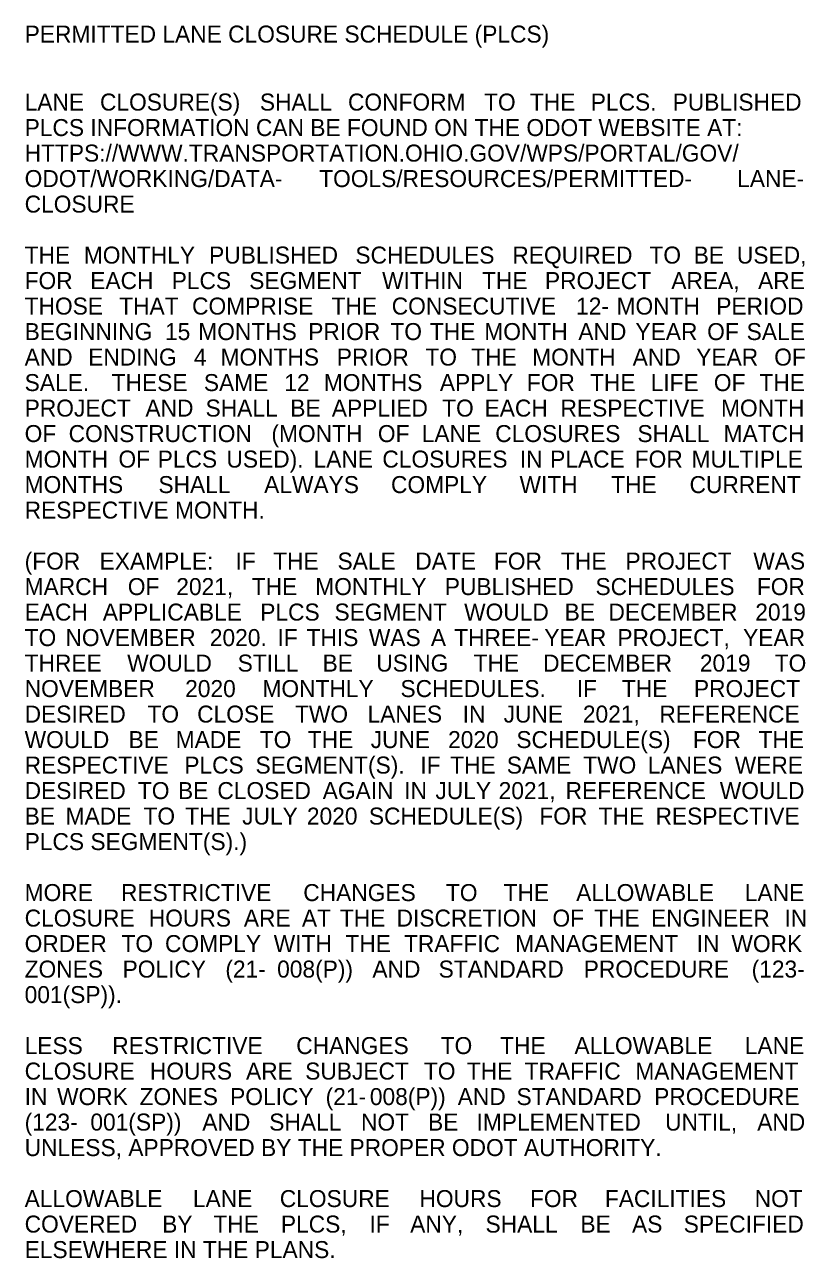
# Model space of a CAD drawing. Extents: x 0 to 43.6, y -18 to 22.
# Drawn here: x 24.66 to 31.08, y -18.01 to -7.85 of the extents above; entities that cross this region are included whole.
import ezdxf

# ---------------------------------------------------------------- set-up
doc = ezdxf.new("R2010")
doc.units = 0
doc.layers.add('SH_Text', color=7, linetype='Continuous')

msp = doc.modelspace()

# ---------------------------------------------------------------- texts
at = {"layer": 'SH_Text'}
for s, p in [('PERMITTED LANE CLOSURE SCHEDULE (PLCS)', (24.66, -8)), ('LANE ', (24.66, -8.56)), ('CLOSURE(S) ', (25.28, -8.56)), ('SHALL ', (26.596, -8.56)), ('CONFORM ', (27.321, -8.56)), ('TO ', (28.441, -8.56)), ('THE ', (28.818, -8.56)), ('PLCS. ', (29.319, -8.56)), ('PUBLISHED ', (29.993, -8.56)), ('PLCS INFORMATION CAN BE FOUND ON THE ODOT WEBSITE AT:', (24.66, -8.77)), ('HTTPS://WWW.TRANSPORTATION.OHIO.GOV/WPS/PORTAL/GOV/ ', (24.66, -8.98)), ('ODOT/WORKING/DATA-', (24.66, -9.19)), ('TOOLS/RESOURCES/PERMITTED-', (27.084, -9.19)), ('LANE-', (30.524, -9.19)), ('CLOSURE', (24.66, -9.4)), ('THE ', (24.66, -9.82)), ('MONTHLY ', (25.147, -9.82)), ('PUBLISHED ', (26.178, -9.82)), ('SCHEDULES ', (27.382, -9.82)), ('REQUIRED ', (28.674, -9.82)), ('TO ', (29.802, -9.82)), ('BE ', (30.166, -9.82)), ('USED, ', (30.522, -9.82)), ('FOR ', (24.66, -10.03)), ('EACH ', (25.2, -10.03)), ('PLCS ', (25.87, -10.03)), ('SEGMENT ', (26.508, -10.03)), ('WITHIN ', (27.602, -10.03)), ('THE ', (28.424, -10.03)), ('PROJECT ', (28.942, -10.03)), ('AREA, ', (29.982, -10.03)), ('ARE ', (30.696, -10.03)), ('THOSE ', (24.66, -10.24)), ('THAT ', (25.438, -10.24)), ('COMPRISE ', (26.038, -10.24)), ('THE ', (27.186, -10.24)), ('CONSECUTIVE ', (27.681, -10.24)), ('12-', (29.198, -10.24)), ('MONTH ', (29.531, -10.24)), ('PERIOD ', (30.352, -10.24)), ('BEGINNING ', (24.66, -10.45)), ('15 ', (25.815, -10.45)), ('MONTHS ', (26.089, -10.45)), ('PRIOR ', (26.994, -10.45)), ('TO ', (27.67, -10.45)), ('THE ', (27.995, -10.45)), ('MONTH ', (28.443, -10.45)), ('AND ', (29.217, -10.45)), ('YEAR ', (29.687, -10.45)), ('OF ', (30.277, -10.45)), ('SALE ', (30.602, -10.45)), ('AND ', (24.66, -10.66)), ('ENDING ', (25.183, -10.66)), ('4 ', (26.053, -10.66)), ('MONTHS ', (26.272, -10.66)), ('PRIOR ', (27.229, -10.66)), ('TO ', (27.958, -10.66)), ('THE ', (28.336, -10.66)), ('MONTH ', (28.837, -10.66)), ('AND ', (29.664, -10.66)), ('YEAR ', (30.187, -10.66)), ('OF ', (30.829, -10.66)), ('SALE.  ', (24.66, -10.87)), ('THESE ', (25.376, -10.87)), ('SAME ', (26.135, -10.87)), ('12 ', (26.797, -10.87)), ('MONTHS ', (27.122, -10.87)), ('APPLY ', (28.077, -10.87)), ('FOR ', (28.793, -10.87)), ('THE ', (29.313, -10.87)), ('LIFE ', (29.812, -10.87)), ('OF ', (30.332, -10.87)), ('THE ', (30.707, -10.87)), ('PROJECT ', (24.66, -11.08)), ('AND ', (25.654, -11.08)), ('SHALL ', (26.149, -11.08)), ('BE ', (26.846, -11.08)), ('APPLIED ', (27.188, -11.08)), ('TO ', (28.096, -11.08)), ('EACH ', (28.445, -11.08)), ('RESPECTIVE ', (29.07, -11.08)), ('MONTH ', (30.391, -11.08)), ('OF ', (24.66, -11.29)), ('CONSTRUCTION ', (25.022, -11.29)), ('(MONTH ', (26.691, -11.29)), ('OF ', (27.567, -11.29)), ('LANE ', (27.928, -11.29)), ('CLOSURES ', (28.533, -11.29)), ('SHALL ', (29.703, -11.29)), ('MATCH ', (30.412, -11.29)), ('MONTH ', (24.66, -11.5)), ('OF ', (25.432, -11.5)), ('PLCS ', (25.755, -11.5)), ('USED). ', (26.321, -11.5)), ('LANE ', (27.038, -11.5)), ('CLOSURES ', (27.604, -11.5)), ('IN ', (28.735, -11.5)), ('PLACE ', (28.985, -11.5)), ('FOR ', (29.681, -11.5)), ('MULTIPLE ', (30.149, -11.5)), ('MONTHS ', (24.66, -11.71)), ('SHALL ', (25.761, -11.71)), ('ALWAYS ', (26.631, -11.71)), ('COMPLY ', (27.675, -11.71)), ('WITH ', (28.733, -11.71)), ('THE ', (29.487, -11.71)), ('CURRENT ', (30.132, -11.71)), ('RESPECTIVE MONTH.', (24.66, -11.92)), ('(FOR ', (24.66, -12.34)), ('EXAMPLE: ', (25.277, -12.34)), ('IF ', (26.395, -12.34)), ('THE ', (26.705, -12.34)), ('SALE ', (27.235, -12.34)), ('DATE ', (27.875, -12.34)), ('FOR ', (28.522, -12.34)), ('THE ', (29.074, -12.34)), ('PROJECT ', (29.605, -12.34)), ('WAS ', (30.657, -12.34)), ('MARCH ', (24.66, -12.55)), ('OF ', (25.509, -12.55)), ('2021, ', (25.908, -12.55)), ('THE ', (26.529, -12.55)), ('MONTHLY ', (27.052, -12.55)), ('PUBLISHED ', (28.118, -12.55)), ('SCHEDULES ', (29.358, -12.55)), ('FOR ', (30.686, -12.55)), ('EACH ', (24.66, -12.76)), ('APPLICABLE ', (25.303, -12.76)), ('PLCS ', (26.599, -12.76)), ('SEGMENT ', (27.21, -12.76)), ('WOULD ', (28.277, -12.76)), ('BE ', (29.104, -12.76)), ('DECEMBER ', (29.465, -12.76)), ('2019 ', (30.673, -12.76)), ('TO ', (24.66, -12.97)), ('NOVEMBER ', (24.996, -12.97)), ('2020. ', (26.184, -12.97)), ('IF ', (26.741, -12.97)), ('THIS ', (26.98, -12.97)), ('WAS ', (27.493, -12.97)), ('A ', (28.003, -12.97)), ('THREE-', (28.195, -12.97)), ('YEAR ', (28.937, -12.97)), ('PROJECT, ', (29.538, -12.97)), ('YEAR ', (30.573, -12.97)), ('THREE ', (24.66, -13.18)), ('WOULD ', (25.504, -13.18)), ('STILL ', (26.413, -13.18)), ('BE ', (27.112, -13.18)), ('USING ', (27.554, -13.18)), ('THE ', (28.355, -13.18)), ('DECEMBER ', (28.927, -13.18)), ('2019 ', (30.217, -13.18)), ('TO ', (30.833, -13.18)), ('NOVEMBER ', (24.66, -13.39)), ('2020 ', (25.981, -13.39)), ('MONTHLY ', (26.617, -13.39)), ('SCHEDULES. ', (27.753, -13.39)), ('IF ', (29.204, -13.39)), ('THE ', (29.575, -13.39)), ('PROJECT ', (30.168, -13.39)), ('DESIRED ', (24.66, -13.6)), ('TO ', (25.671, -13.6)), ('CLOSE ', (26.08, -13.6)), ('TWO ', (26.885, -13.6)), ('LANES ', (27.482, -13.6)), ('IN ', (28.265, -13.6)), ('JUNE ', (28.602, -13.6)), ('2021, ', (29.254, -13.6)), ('REFERENCE ', (29.884, -13.6)), ('WOULD ', (24.66, -13.81)), ('BE ', (25.515, -13.81)), ('MADE ', (25.903, -13.81)), ('TO ', (26.595, -13.81)), ('THE ', (26.99, -13.81)), ('JUNE ', (27.508, -13.81)), ('2020 ', (28.145, -13.81)), ('SCHEDULE(S) ', (28.707, -13.81)), ('FOR ', (30.16, -13.81)), ('THE ', (30.7, -13.81)), ('RESPECTIVE ', (24.66, -14.02)), ('PLCS ', (25.974, -14.02)), ('SEGMENT(S). ', (26.56, -14.02)), ('IF ', (27.917, -14.02)), ('THE ', (28.162, -14.02)), ('SAME ', (28.628, -14.02)), ('TWO ', (29.257, -14.02)), ('LANES ', (29.788, -14.02)), ('WERE ', (30.504, -14.02)), ('DESIRED ', (24.66, -14.23)), ('TO ', (25.592, -14.23)), ('BE ', (25.922, -14.23)), ('CLOSED ', (26.246, -14.23)), ('AGAIN ', (27.113, -14.23)), ('IN ', (27.784, -14.23)), ('JULY ', (28.041, -14.23)), ('2021, ', (28.561, -14.23)), ('REFERENCE ', (29.112, -14.23)), ('WOULD ', (30.381, -14.23)), ('BE ', (24.66, -14.44)), ('MADE ', (24.997, -14.44)), ('TO ', (25.638, -14.44)), ('THE ', (25.982, -14.44)), ('JULY ', (26.45, -14.44)), ('2020 ', (26.983, -14.44)), ('SCHEDULE(S) ', (27.493, -14.44)), ('FOR ', (28.896, -14.44)), ('THE ', (29.384, -14.44)), ('RESPECTIVE ', (29.852, -14.44)), ('PLCS SEGMENT(S).)', (24.66, -14.65)), ('MORE ', (24.66, -15.07)), ('RESTRICTIVE ', (25.453, -15.07)), ('CHANGES ', (26.953, -15.07)), ('TO ', (28.127, -15.07)), ('THE ', (28.602, -15.07)), ('ALLOWABLE ', (29.199, -15.07)), ('LANE ', (30.587, -15.07)), ('CLOSURE ', (24.66, -15.28)), ('HOURS ', (25.682, -15.28)), ('ARE ', (26.464, -15.28)), ('AT ', (26.942, -15.28)), ('THE ', (27.254, -15.28)), ('DISCRETION ', (27.721, -15.28)), ('OF ', (29.004, -15.28)), ('THE ', (29.348, -15.28)), ('ENGINEER ', (29.815, -15.28)), ('IN ', (30.913, -15.28)), ('ORDER ', (24.66, -15.49)), ('TO ', (25.457, -15.49)), ('COMPLY ', (25.815, -15.49)), ('WITH ', (26.71, -15.49)), ('THE ', (27.3, -15.49)), ('TRAFFIC ', (27.782, -15.49)), ('MANAGEMENT ', (28.698, -15.49)), ('IN ', (30.191, -15.49)), ('WORK ', (30.477, -15.49)), ('ZONES ', (24.66, -15.7)), ('POLICY ', (25.466, -15.7)), ('(21-', (26.312, -15.7)), ('008(P)) ', (26.738, -15.7)), ('AND ', (27.522, -15.7)), ('STANDARD ', (28.067, -15.7)), ('PROCEDURE ', (29.261, -15.7)), ('(123-', (30.643, -15.7)), ('001(SP)).', (24.66, -15.91)), ('LESS ', (24.66, -16.33)), ('RESTRICTIVE ', (25.381, -16.33)), ('CHANGES ', (26.895, -16.33)), ('TO ', (28.084, -16.33)), ('THE ', (28.573, -16.33)), ('ALLOWABLE ', (29.185, -16.33)), ('LANE ', (30.587, -16.33)), ('CLOSURE ', (24.66, -16.54)), ('HOURS ', (25.691, -16.54)), ('ARE ', (26.482, -16.54)), ('SUBJECT ', (26.969, -16.54)), ('TO ', (27.946, -16.54)), ('THE ', (28.299, -16.54)), ('TRAFFIC ', (28.775, -16.54)), ('MANAGEMENT ', (29.686, -16.54)), ('IN ', (24.66, -16.75)), ('WORK ', (24.927, -16.75)), ('ZONES ', (25.606, -16.75)), ('POLICY ', (26.351, -16.75)), ('(21-', (27.137, -16.75)), ('008(P)) ', (27.501, -16.75)), ('AND ', (28.224, -16.75)), ('STANDARD ', (28.708, -16.75)), ('PROCEDURE ', (29.841, -16.75)), ('(123-', (24.66, -16.96)), ('001(SP)) ', (25.201, -16.96)), ('AND ', (26.122, -16.96)), ('SHALL ', (26.673, -16.96)), ('NOT ', (27.428, -16.96)), ('BE ', (27.98, -16.96)), ('IMPLEMENTED ', (28.379, -16.96)), ('UNTIL, ', (29.931, -16.96)), ('AND ', (30.689, -16.96)), ('UNLESS, APPROVED BY THE PROPER ODOT AUTHORITY.', (24.66, -17.17)), ('ALLOWABLE ', (24.66, -17.59)), ('LANE ', (26.045, -17.59)), ('CLOSURE ', (26.76, -17.59)), ('HOURS ', (27.909, -17.59)), ('FOR ', (28.819, -17.59)), ('FACILITIES ', (29.435, -17.59)), ('NOT ', (30.668, -17.59)), ('COVERED ', (24.66, -17.8)), ('BY ', (25.792, -17.8)), ('THE ', (26.213, -17.8)), ('PLCS, ', (26.769, -17.8)), ('IF ', (27.498, -17.8)), ('ANY, ', (27.833, -17.8)), ('SHALL ', (28.453, -17.8)), ('BE ', (29.234, -17.8)), ('AS ', (29.659, -17.8)), ('SPECIFIED ', (30.084, -17.8)), ('ELSEWHERE IN THE PLANS.', (24.66, -18.01))]:
    msp.add_text(s, height=0.14, dxfattribs=at).set_placement(p)

doc.saveas('drawing.dxf')
